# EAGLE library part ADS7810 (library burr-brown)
12-Bit 800kHz Sampling CMOS ADC
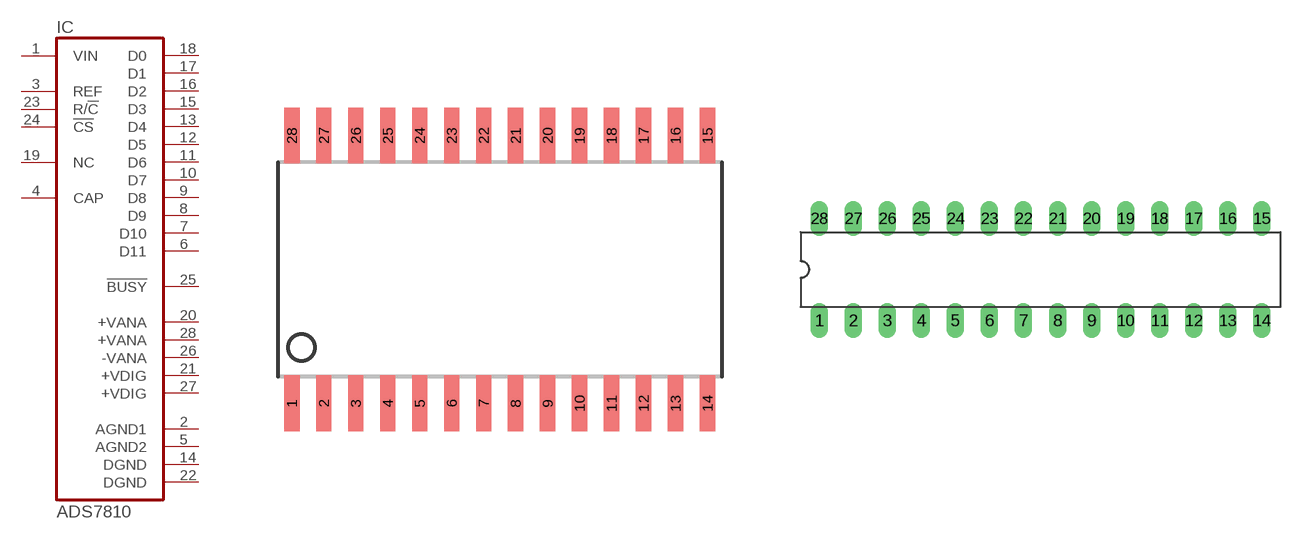
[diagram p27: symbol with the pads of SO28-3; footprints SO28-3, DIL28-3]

Designator prefix IC

## ADS7810U (MF: TEXAS INSTRUMENTS; MPN: ADS7810U; OC_FARNELL: 1509511; OC_NEWARK: 73C9220)  [SO28-3]
1  VIN  in
2  AGND1  pwr
3  REF
4  CAP  pas
5  AGND2  pwr
6  D11  out
7  D10  out
8  D9  out
9  D8  out
10  D7  out
11  D6  out
12  D5  out
13  D4  out
14  DGND  pwr
15  D3  out
16  D2  out
17  D1  out
18  D0  out
19  NC  nc
20  +VANA  pwr
21  +VDIG  pwr
22  DGND  pwr
23  R/!C  in
24  !CS  in
25  !BUSY  out
26  -VANA  pwr
27  +VDIG  pwr
28  +VANA  pwr

## ADS7810P (OC_FARNELL: unknown; OC_NEWARK: unknown)  [DIL28-3]
Pads as for SO28-3

## Footprint SO28-3 (pad centres in mm)
Small Outline Package
smd 0.61 x 2.21: 1 -8.255,-5.315; 2 -6.985,-5.315; 3 -5.715,-5.315; 4 -4.445,-5.315; 5 -3.175,-5.315; 6 -1.905,-5.315; 7 -0.635,-5.315; 8 0.635,-5.315; 9 1.905,-5.315; 10 3.175,-5.315; 11 4.445,-5.315; 12 5.715,-5.315; 13 6.985,-5.315; 14 8.255,-5.315; 15 8.255,5.315; 16 6.985,5.315; 17 5.715,5.315; 18 4.445,5.315; 19 3.175,5.315; 20 1.905,5.315; 21 0.635,5.315; 22 -0.635,5.315; 23 -1.905,5.315; 24 -3.175,5.315; 25 -4.445,5.315; 26 -5.715,5.315; 27 -6.985,5.315; 28 -8.255,5.315

## Footprint DIL28-3 (pad centres in mm)
Dual In Line 0.3 inch
drill 0.813 long: 1 -16.51,-3.81; 2 -13.97,-3.81; 3 -11.43,-3.81; 4 -8.89,-3.81; 5 -6.35,-3.81; 6 -3.81,-3.81; 7 -1.27,-3.81; 8 1.27,-3.81; 9 3.81,-3.81; 10 6.35,-3.81; 11 8.89,-3.81; 12 11.43,-3.81; 13 13.97,-3.81; 14 16.51,-3.81; 15 16.51,3.81; 16 13.97,3.81; 17 11.43,3.81; 18 8.89,3.81; 19 6.35,3.81; 20 3.81,3.81; 21 1.27,3.81; 22 -1.27,3.81; 23 -3.81,3.81; 24 -6.35,3.81; 25 -8.89,3.81; 26 -11.43,3.81; 27 -13.97,3.81; 28 -16.51,3.81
